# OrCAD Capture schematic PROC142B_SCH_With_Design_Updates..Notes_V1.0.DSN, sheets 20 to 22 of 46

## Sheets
20 19. M.2 INTERFACE: size C; title: M.2 INTERFACE AND CONNECTOR
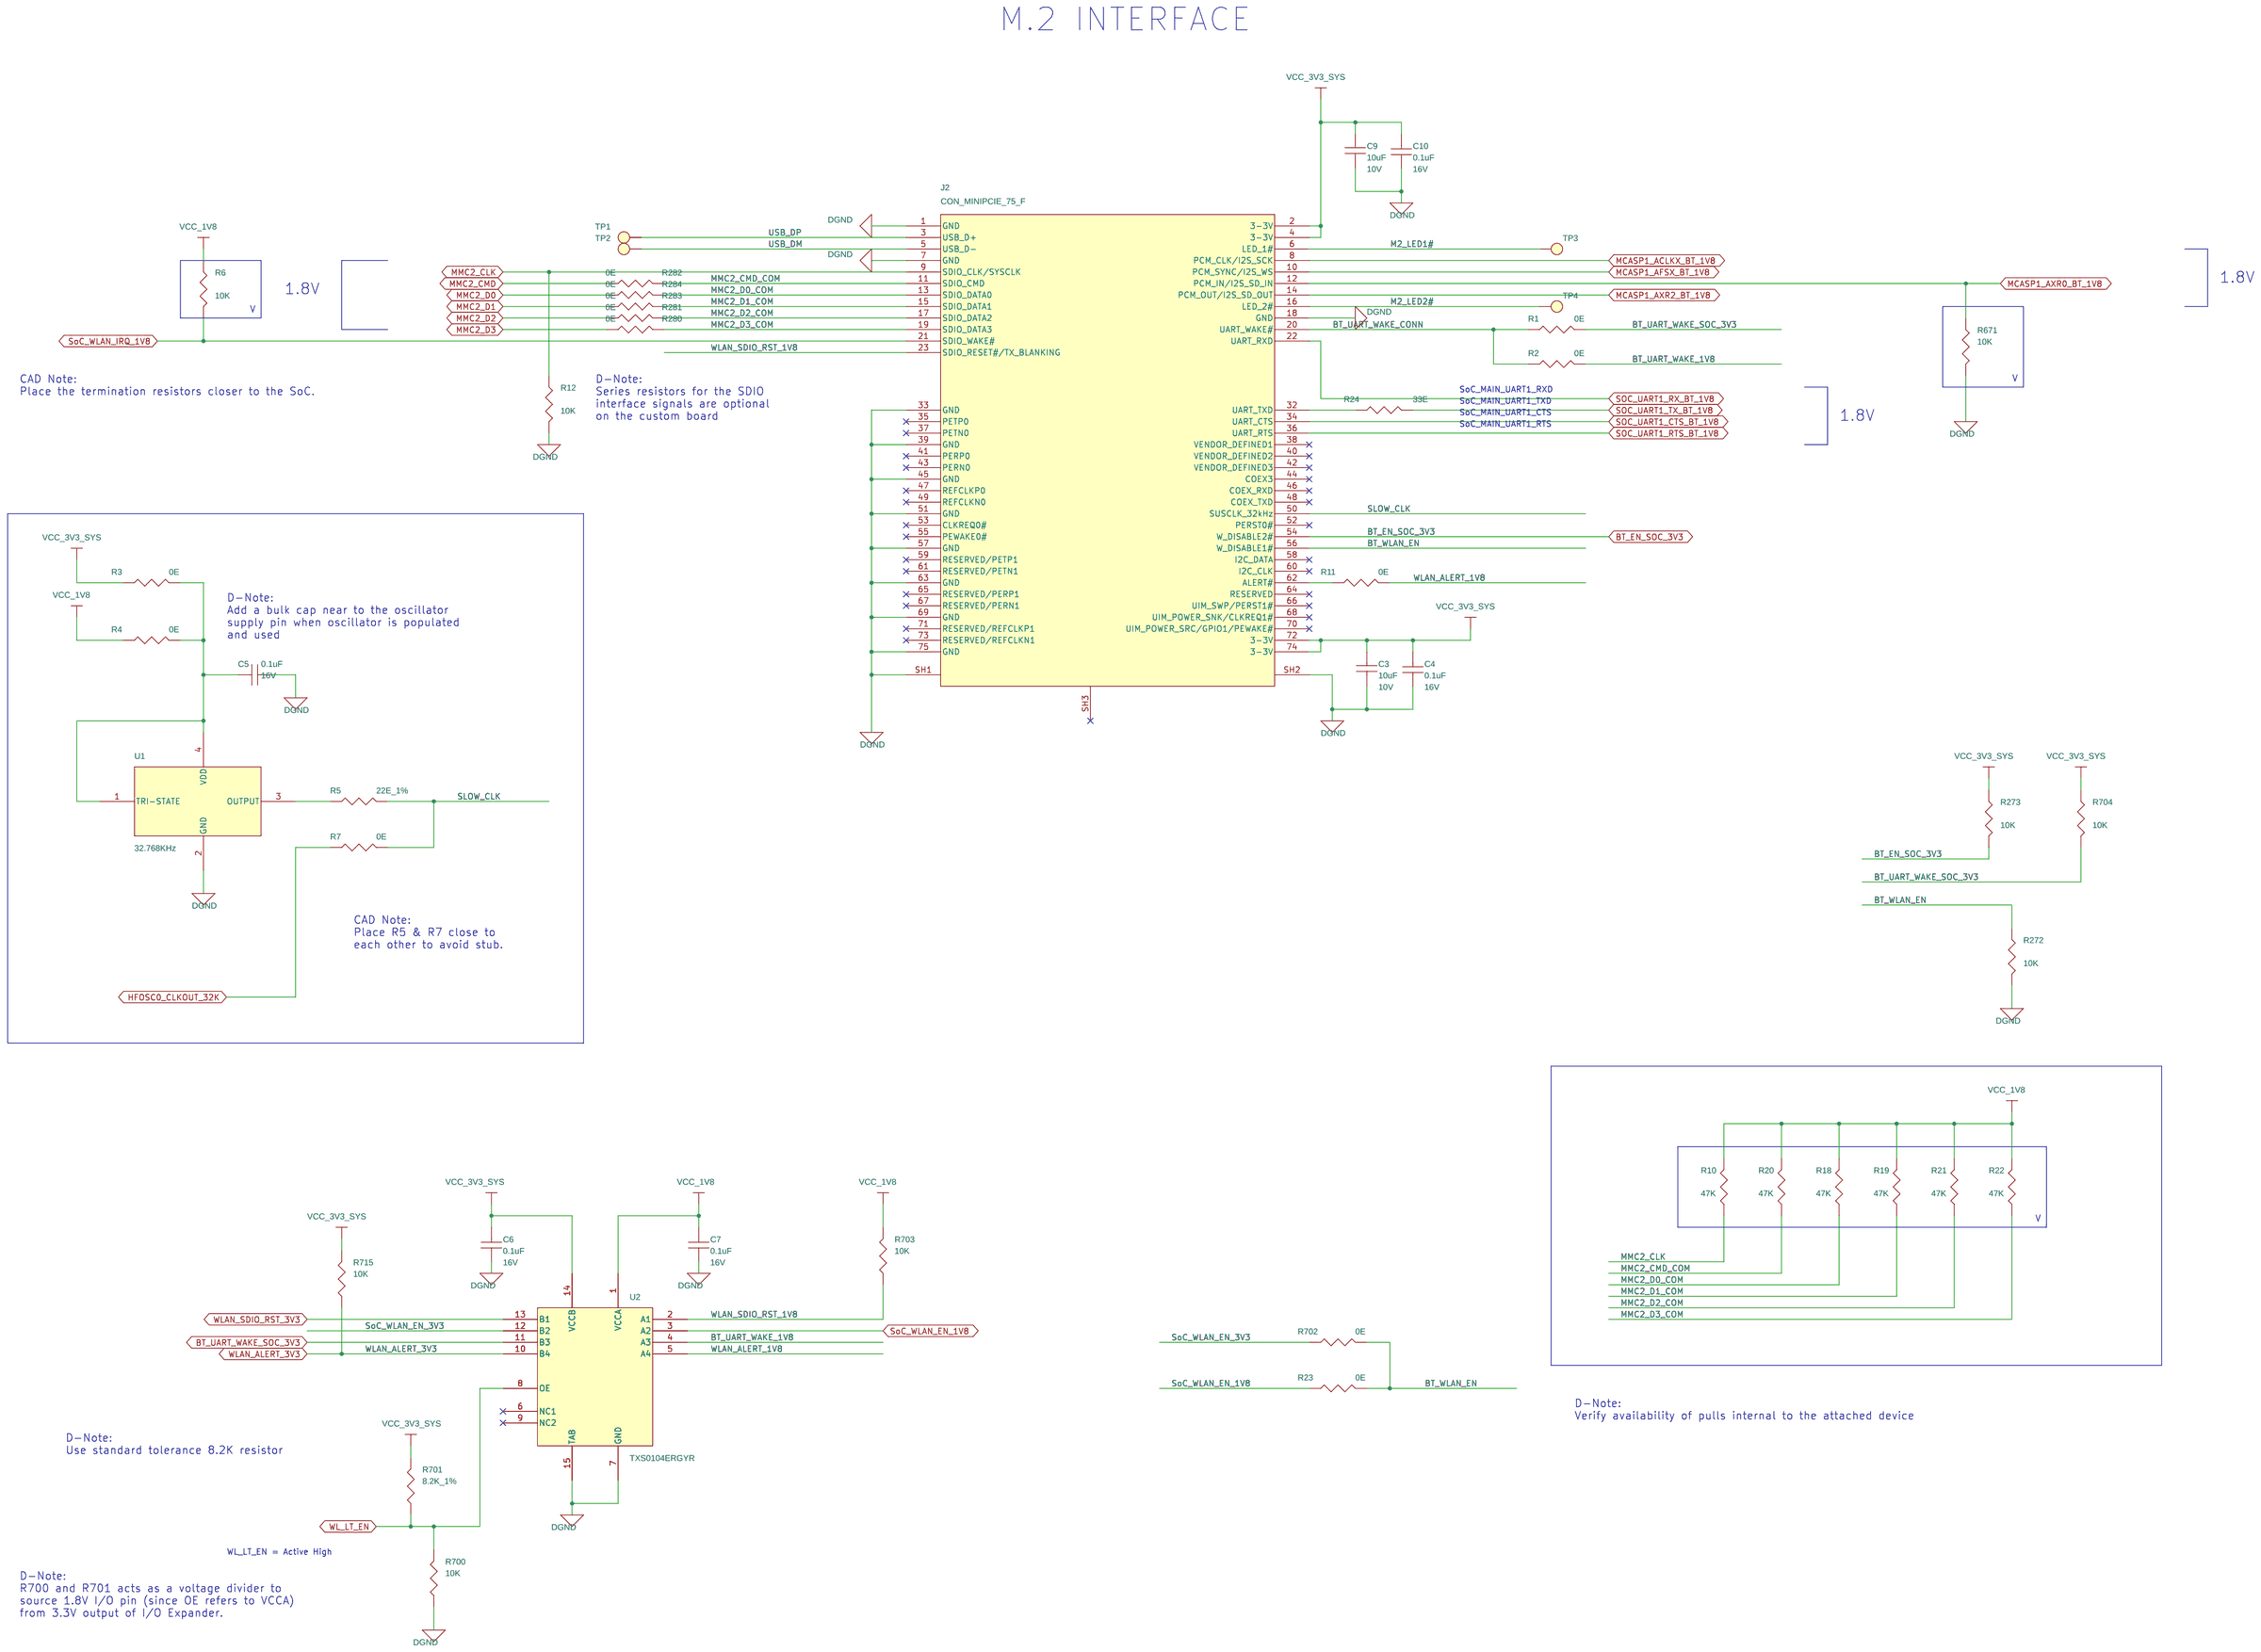
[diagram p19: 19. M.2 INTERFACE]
21 20. eMMC FLASH: size C; title: SOC MMC0.2 INTERFACE AND eMMC FLASH + RESET
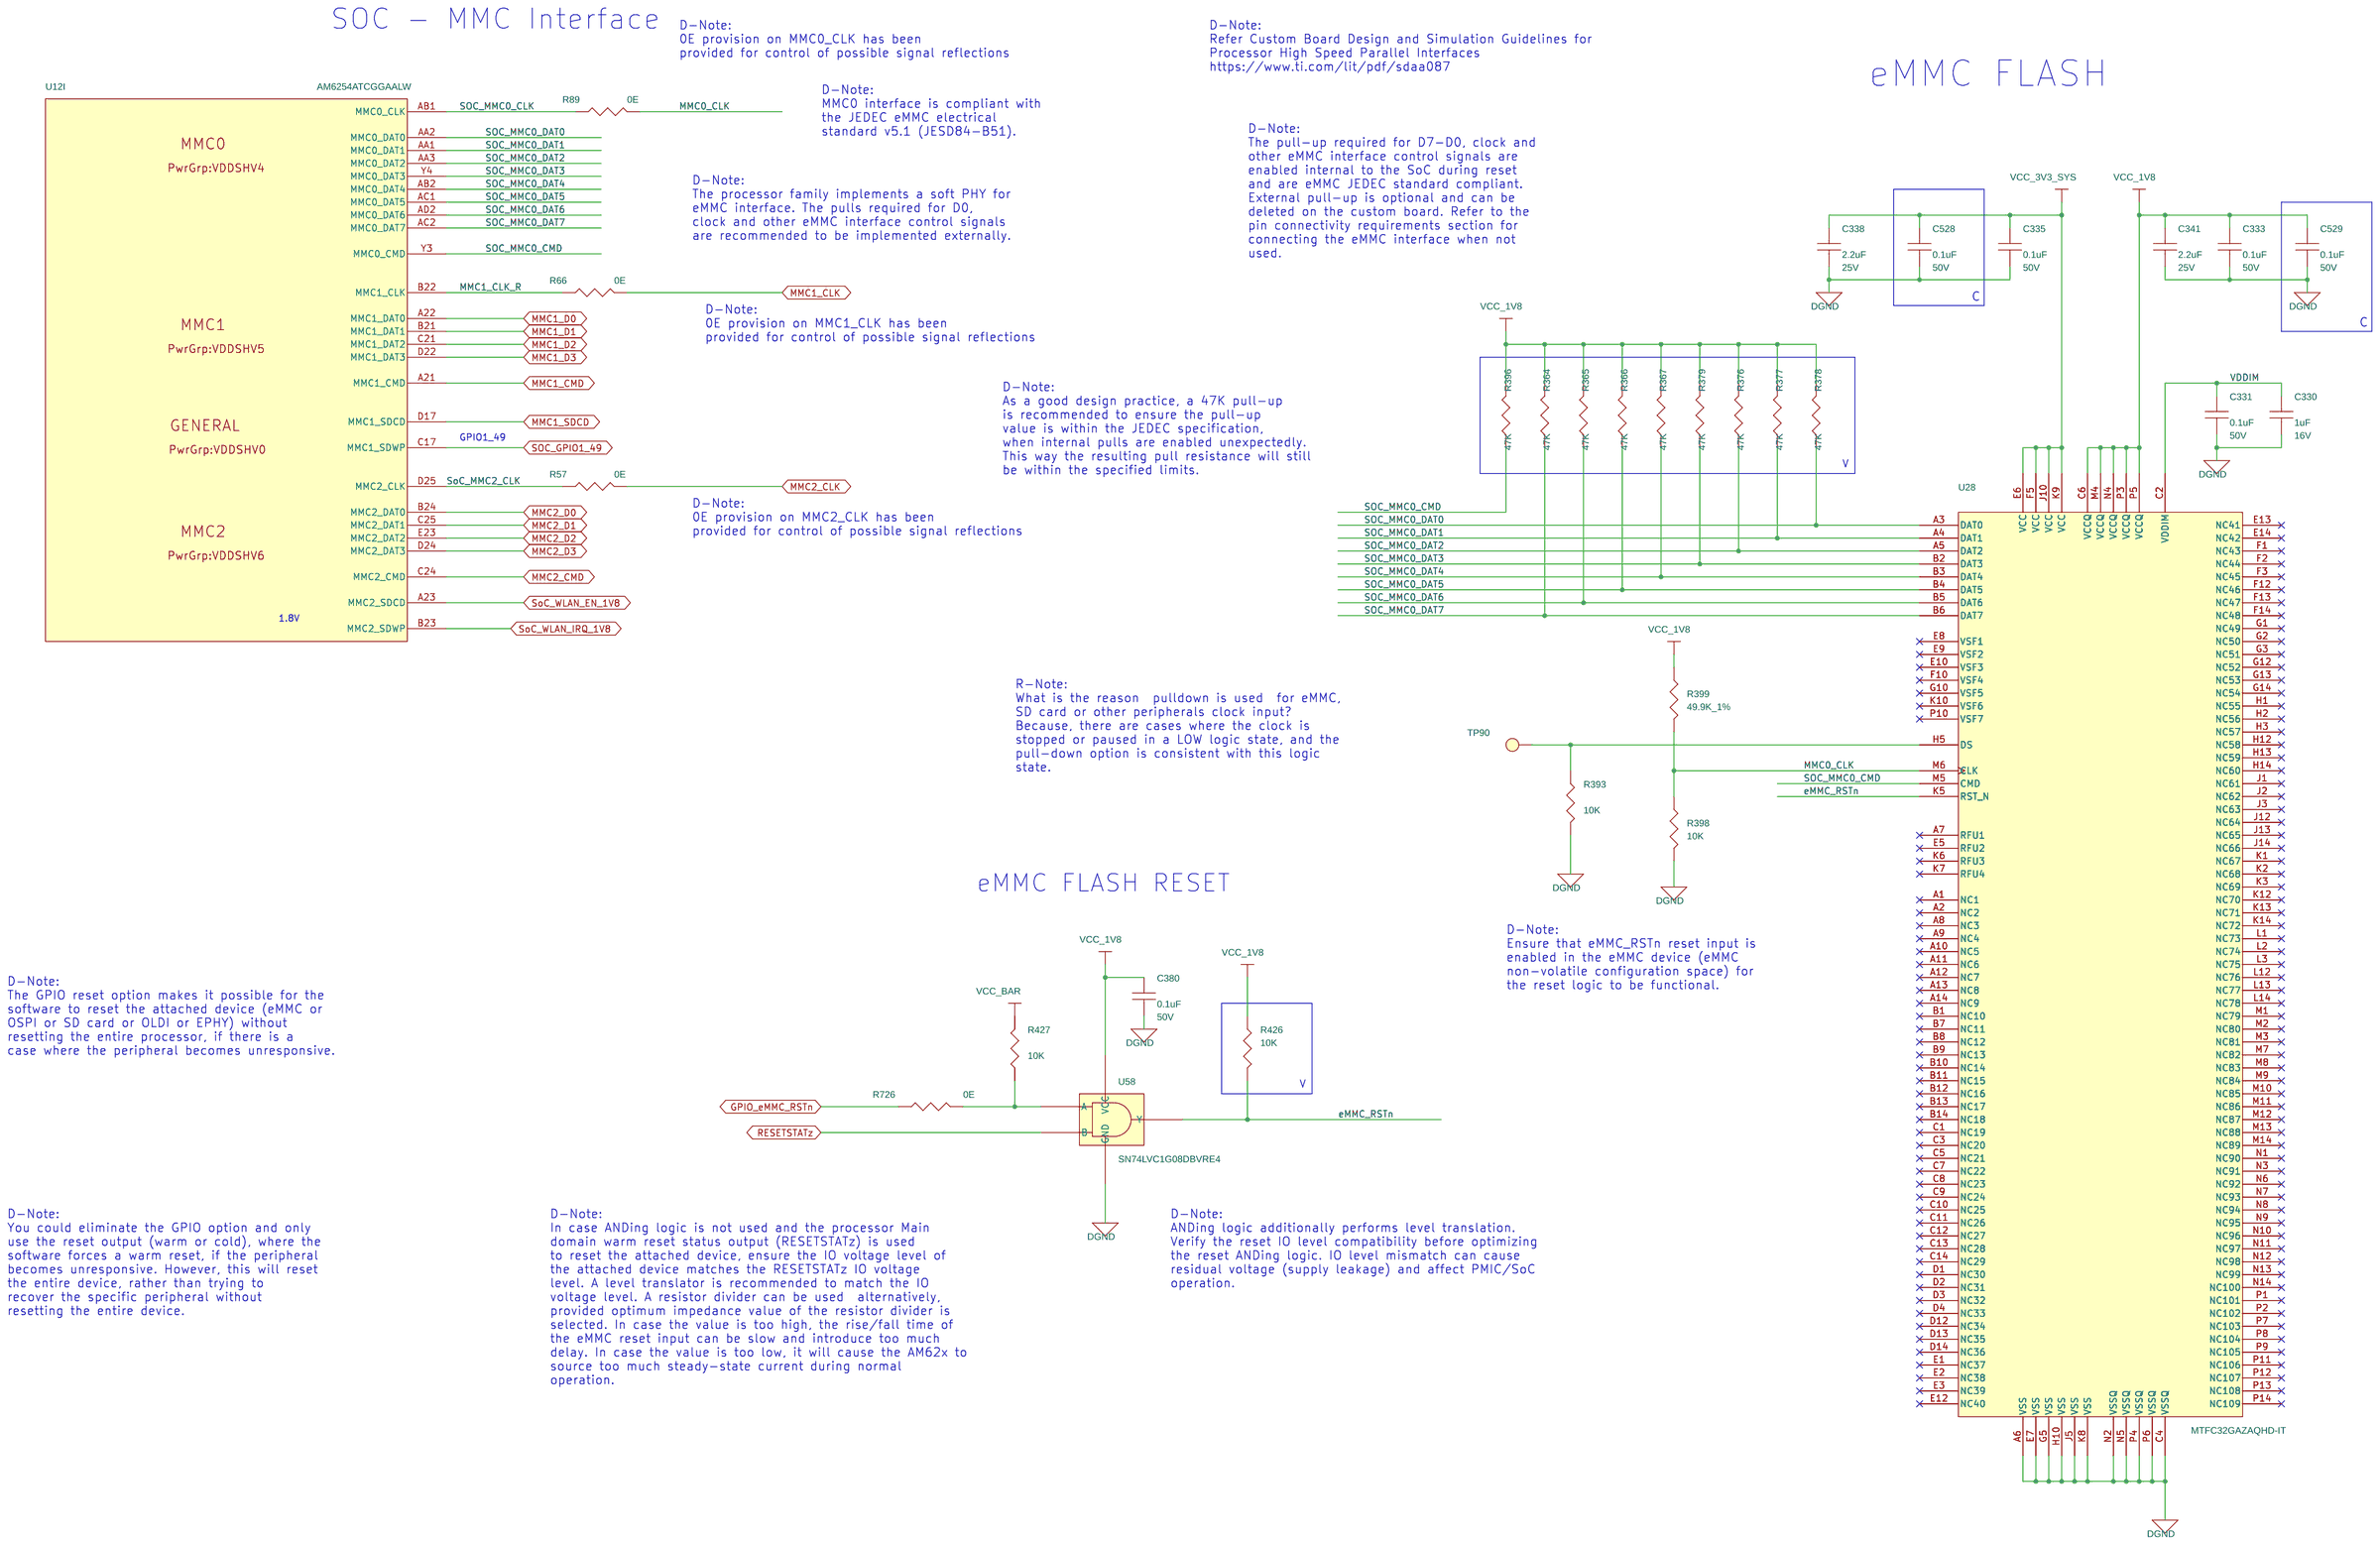
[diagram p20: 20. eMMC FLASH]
22 21. SD CARD INTERFACE: size C; title: SD CARD-LOAD SWITCH, LOAD SWITCH RESET LOGIC AND DATA INTERFACE
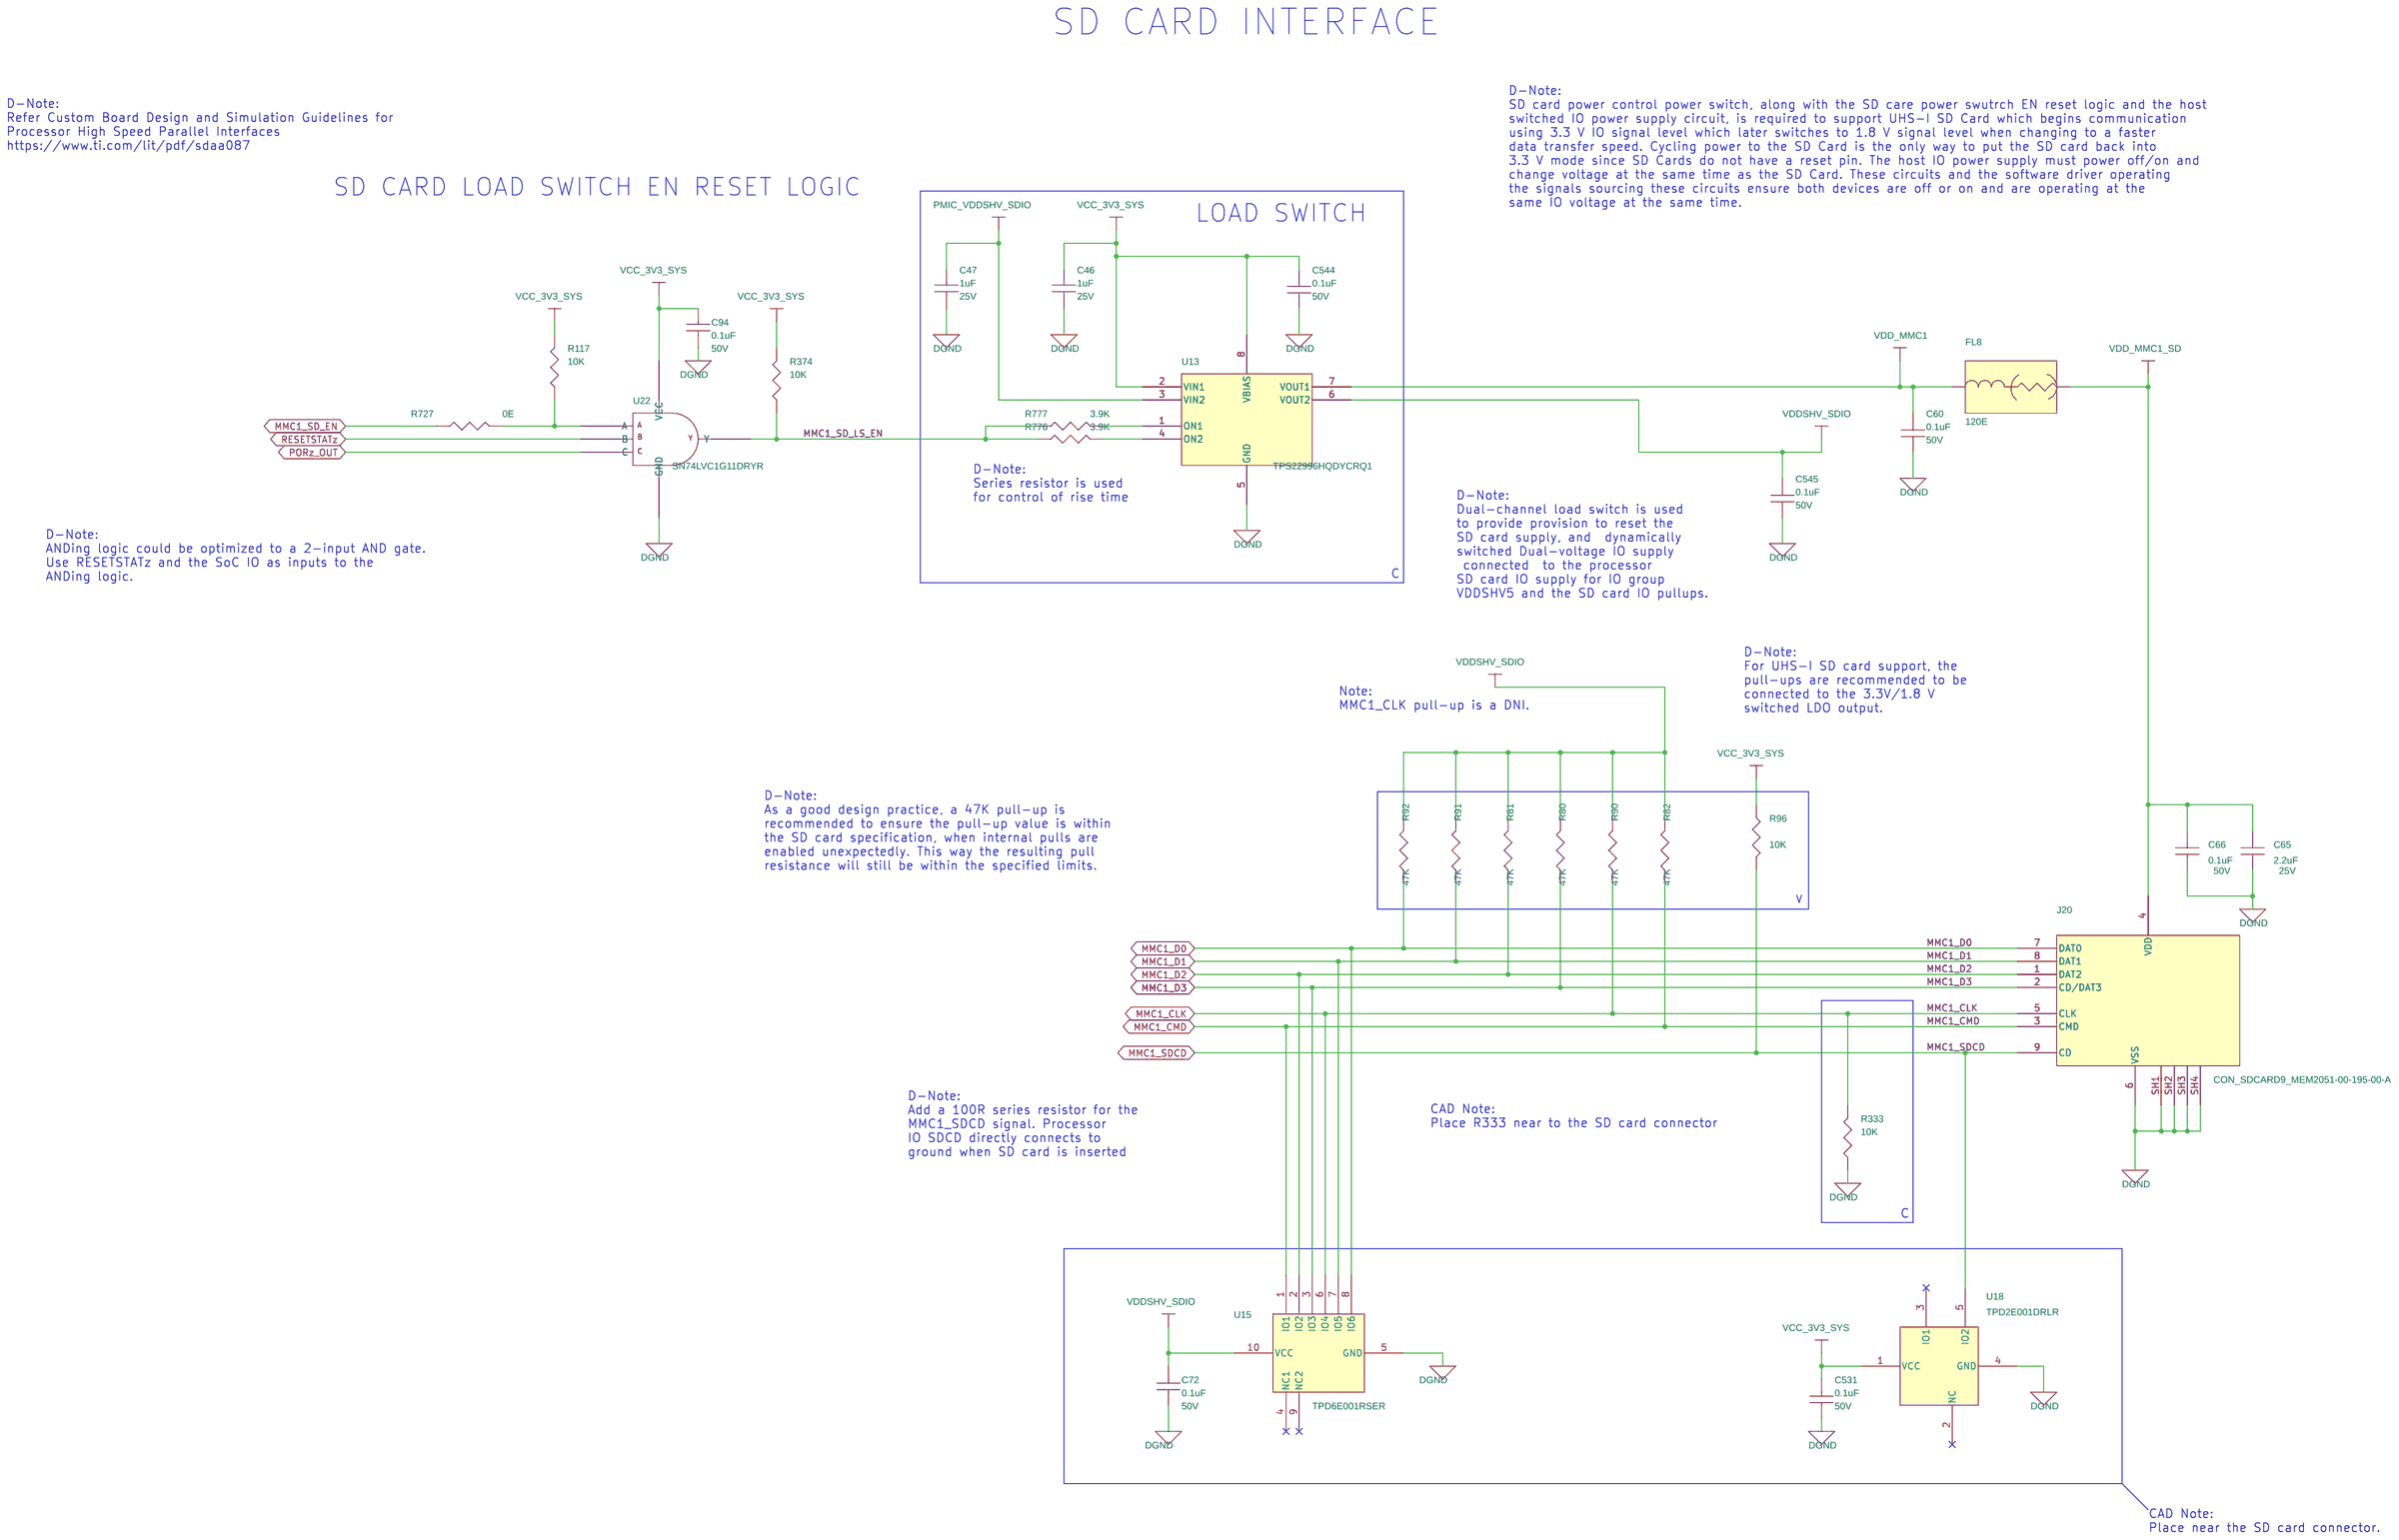
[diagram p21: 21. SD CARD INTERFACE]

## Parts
sheet 19. M.2 INTERFACE
C3  10uF  [CAP0402_0-75]
C4  0.1uF  [CAP0201_0-5]
C5  0.1uF  [CAP0201_0-5]
C6  0.1uF  [CAP0201_0-5]
C7  0.1uF  [CAP0201_0-5]
C9  10uF  [CAP0402_0-75]
C10  0.1uF  [CAP0201_0-5]
J2  CON_MINIPCIE_75_F  [CON_MINIPCI75_2199119-4_S_R_S_3-2_2230]
R1  0E  [RES0201_0-5]
R2  0E  [RES0201_0-5]
R3  0E  [RES0201_0-5]
R4  0E  [RES0201_0-5]
R5  22E_1%  [RES0201_0-5]
R6  10K  [RES0201_0-5]
R7  0E  [RES0201_0-5]
R10  47K  [RES0402_0-5]
R11  0E  [RES0201_0-5]
R12  10K  [RES0201_0-5]
R18  47K  [RES0402_0-5]
R19  47K  [RES0402_0-5]
R20  47K  [RES0402_0-5]
R21  47K  [RES0402_0-5]
R22  47K  [RES0402_0-5]
R23  0E  [RES0201_0-5]
R24  33E  [RES0201_0-5]
R272  10K  [RES0402_0-5]
R273  10K  [RES0402_0-5]
R280  0E  [RES0402_0-5]
R281  0E  [RES0402_0-5]
R282  0E  [RES0402_0-5]
R283  0E  [RES0402_0-5]
R284  0E  [RES0402_0-5]
R671  10K  [RES0402_0-5]
R700  10K  [RES0201_0-5]
R701  8.2K_1%  [RES0201_0-5]
R702  0E  [RES0201_0-5]
R703  10K  [RES0201_0-5]
R704  10K  [RES0402_0-5]
R715  10K  [RES0201_0-5]
TP1  TP20_SMD  [TP20_SMD]
TP2  TP20_SMD  [TP20_SMD]
TP3  TP20_SMD  [TP20_SMD]
TP4  TP20_SMD  [TP20_SMD]
U1  32.768KHz  [OSC4_ASDK_105X85_SMD]
U2  TXS0104ERGYR  [QFN14_19-68_145X145]
sheet 20. eMMC FLASH
C330  1uF  [CAP0201_0-5]
C331  0.1uF  [CAP0402_0-75]
C333  0.1uF  [CAP0402_0-75]
C335  0.1uF  [CAP0402_0-75]
C338  2.2uF  [CAP0402_0-75]
C341  2.2uF  [CAP0402_0-75]
C380  0.1uF  [CAP0402_0-75]
C528  0.1uF  [CAP0402_0-75]
C529  0.1uF  [CAP0402_0-75]
R57  0E  [RES0201_0-5]
R66  0E  [RES0201_0-5]
R89  0E  [RES0201_0-5]
R364  47K  [RES0402_0-5]
R365  47K  [RES0402_0-5]
R366  47K  [RES0402_0-5]
R367  47K  [RES0402_0-5]
R376  47K  [RES0402_0-5]
R377  47K  [RES0402_0-5]
R378  47K  [RES0402_0-5]
R379  47K  [RES0402_0-5]
R393  10K  [RES0201_0-5]
R396  47K  [RES0402_0-5]
R398  10K  [RES0201_0-5]
R399  49.9K_1%  [RES0402_0-5]
R426  10K  [RES0402_0-5]
R427  10K  [RES0201_0-5]
R726  0E  [RES0402_0-5]
TP90  TP20_SMD  [TP20_SMD]
U28  MTFC32GAZAQHD-IT  [VFBGA153_19-68_460X520_0-9]
U58  SN74LVC1G08DBVRE4  [SOT23-5]
sheet 21. SD CARD INTERFACE
C46  1uF  [CAP0402_0-75]
C47  1uF  [CAP0402_0-75]
C60  0.1uF  [CAP0402_0-75]
C65  2.2uF  [CAP0402_0-75]
C66  0.1uF  [CAP0402_0-75]
C72  0.1uF  [CAP0402_0-75]
C94  0.1uF  [CAP0402_0-75]
C531  0.1uF  [CAP0402_0-75]
C544  0.1uF  [CAP0402_0-75]
C545  0.1uF  [CAP0402_0-75]
FL8  120E  [EMIFIL_BLM15A_0402_0-6]
J20  CON_SDCARD9_MEM2051-00-195-00-A  [CON_SD9_MEM2051-00-195-00_S_R_S_2-1]
R80  47K  [RES0402_0-5]
R81  47K  [RES0402_0-5]
R82  47K  [RES0402_0-5]
R90  47K  [RES0402_0-5]
R91  47K  [RES0402_0-5]
R92  47K  [RES0402_0-5]
R96  10K  [RES0402_0-5]
R117  10K  [RES0201_0-5]
R333  10K  [RES0201_0-5]
R374  10K  [RES0201_0-5]
R727  0E  [RES0402_0-5]
R776  3.9K  [RES0402_0-5]
R777  3.9K  [RES0402_0-5]
U13  TPS22996HQDYCRQ1  [SOT5X3-8_0-6]
U15  TPD6E001RSER  [UQFN10_19-68_80X60_0-6]
U18  TPD2E001DRLR  [SOT553-5_0-6]
U22  SN74LVC1G11DRYR  [SON6_SN74LVC2G17_40X60_0-6]
sheet 43. HDMI INTERFACE
U12  AM6254ATCGGAALW  [BGA425_19-68_510X510_0-7]  (sections A,B,C,D,E,F,G,H,I,J,K,L,M,N,O,P,Q,R)

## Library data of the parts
C3 C9 = CAP: CAP CERAMIC 10uF 10V 20% X5R 0402; Chkd/date: MANIRAJA/300520; Crtd /date: ALVY/260520; Custom_Duty: 15%; Customs_HS_Code: 85322990; Distributor_name: DIGIKEY; Distributor_part_number: 490-GRM155R61A106ME11DTR-ND; Footprint Path: Y:\MIS_DATABASE\Library\ALTIUM_TOOL\PCB_FOOTPRINTS\Altium_Footprint_Lib.PcbLib; Height: 0.55MM; Library Path: Y:\MIS_DATABASE\Library\ALTIUM_TOOL\SCHEMATICS_PARTS\MS_DISCRETE_Library.schlib; Mfr_name: MURATA; Mfr_part_number: GRM155R61A106ME11D; Mistral Part No: 120013110019-R; Package: 0402; Part_type: CAPACITORS\CERAMIC; Project: QCS610_NANOSOM; RoHS: RoHS; Temperature: -55°C+85°C; Tolerance: 20%; Voltage: 10V; Wattage: NA; Weight: 3.1mg; Datasheet: Y:\MIS_DATABASE\DATASHEETS\CAPACITORS\MURATA-GXX-SER_NOV17.PDF
C4-C7 C10 = CAP: CAP CERAMIC 0.1uF 16V 10% X5R 0201; Alt_Mfr_name: YAGEO AMERICA; Alt_Mfr_part_number: CC0402KRX5R8BB104; Chkd/date: MANIRAJA/230118; Crtd /date: MANIRAJA/230118; Custom_Duty: 15%; Customs_HS_Code: 85322990; Distributor_name: DIGIKEY; Distributor_part_number: 490-14305-1-ND; Footprint Path: Y:\MIS_DATABASE\Library\ALTIUM_TOOL\PCB_FOOTPRINTS\Altium_Footprint_Lib.PcbLib; Height: 0.33MM; Library Path: Y:\MIS_DATABASE\Library\ALTIUM_TOOL\SCHEMATICS_PARTS\MS_DISCRETE_Library.schlib; Mfr_name: MURATA; Mfr_part_number: GRM033R61C104KE14D; Mistral Part No: 120009030072-R; Package: 0201; Part_type: CAPACITORS\CERAMIC; Project: TI_MAXIE_CPB; RoHS: RoHS; Temperature: -55°C+85°C; Tolerance: 10%; Voltage: 16V; Wattage: NA; Weight: 0.33mg; Datasheet: Y:\MIS_DATABASE\DATASHEETS\CAPACITORS\GRM033R61C104KE14.PDF
J2 = CON_PCI_75_2199119-4_2230: CON MINIPCI 75POS 0.50MM PITCH FEMALE RT SMD; Chkd/date: ALVY/300521; Crtd /date: ALVY/300521; Custom_Duty: 24%; Customs_HS_Code: 85369090; Distributor_name: DIGIKEY; Distributor_part_number: A115900CT-ND; Footprint Path: Y:\MIS_DATABASE\Library\ALTIUM_TOOL\PCB_FOOTPRINTS\Altium_Footprint_Lib.PcbLib; Height: 3.20MM; Library Path: Y:\MIS_DATABASE\Library\ALTIUM_TOOL\SCHEMATICS_PARTS\MS_CONNECTOR_Library.schlib; Mfr_name: TE CONNECTIVITY; Mfr_part_number: 2199119-4_2230; Mistral Part No: 150021030016-R; Package: SMD; Part_type: CONNECTOR\PCI; Project: VOLTA_CHARGER V5; RoHS: RoHS; Temperature: -40°C+80°C; Tolerance: NA; Voltage: NA; Wattage: NA; Weight: 506mg; Datasheet: Y:\MIS_DATABASE\DATASHEETS\CONNECTORS\2199119.PDF
R1-R4 R7 R11 R23 R702 = RESISTOR: RES 0E 1/20W 5% 0201; Chkd/date: NAVEED/301214; Crtd /date: MUDDU/120710; Custom_Duty: 15%; Customs_HS_Code: 85332119; Distributor_name: DIGIKEY; Distributor_part_number: 311-0.0NCT-ND; Footprint Path: Y:\MIS_DATABASE\Library\ALTIUM_TOOL\PCB_FOOTPRINTS\Altium_Footprint_Lib.PcbLib; Height: 0.26MM; Library Path: Y:\MIS_DATABASE\Library\ALTIUM_TOOL\SCHEMATICS_PARTS\MS_DISCRETE_Library.schlib; Mfr_name: YAGEO AMERICA; Mfr_part_number: RC0201JR-070RL; Mistral Part No: 110010070067-R; Package: 0201; Part_type: RESISTORS\FIXED; Project: PB_BUGBASE; RoHS: RoHS; Temperature: -55°C+125°C; Tolerance: 5%; Voltage: NA; Wattage: 1/20W; Weight: 0.17mg; Datasheet: Y:\MIS_DATABASE\DATASHEETS\RESISTORS\RCXXXXL-SER_MAR18.PDF
R5 = RESISTOR: RES 22E 1/20W 1% 0201; Chkd/date: MAZHAR/140709; Crtd /date: MAZHAR/220807; Custom_Duty: 15%; Customs_HS_Code: 85332119; Distributor_name: DIGIKEY; Distributor_part_number: P22.0ABCT-ND; Footprint Path: Y:\MIS_DATABASE\Library\ALTIUM_TOOL\PCB_FOOTPRINTS\Altium_Footprint_Lib.PcbLib; Height: 0.26MM; Library Path: Y:\MIS_DATABASE\Library\ALTIUM_TOOL\SCHEMATICS_PARTS\MS_DISCRETE_Library.schlib; Mfr_name: PANASONIC-ECG; Mfr_part_number: ERJ-1GEF22R0C; Mistral Part No: 110009030522-R; Package: 0201; Part_type: RESISTORS\FIXED; Project: V8TS; RoHS: RoHS; Temperature: -55°C+125°C; Tolerance: 1%; Voltage: NA; Wattage: 1/20W; Weight: 0.15mg; Datasheet: Y:\MIS_DATABASE\DATASHEETS\RESISTORS\PAN-ERJSER_NOV17.PDF
R6 R12 R117 R333 R374 R393 R398 R427 R700 R703 R715 = RESISTOR: RES 10K 1/20W 5% 0201; Chkd/date: MANIRAJA/050517; Crtd /date: MANIRAJA/050517; Custom_Duty: 15%; Customs_HS_Code: 85332119; Distributor_name: DIGIKEY; Distributor_part_number: 311-10KNCT-ND; Footprint Path: Y:\MIS_DATABASE\Library\ALTIUM_TOOL\PCB_FOOTPRINTS\Altium_Footprint_Lib.PcbLib; Height: 0.26MM; Library Path: Y:\MIS_DATABASE\Library\ALTIUM_TOOL\SCHEMATICS_PARTS\MS_DISCRETE_Library.schlib; Mfr_name: YAGEO AMERICA; Mfr_part_number: RC0201JR-0710KL; Mistral Part No: 110010070051-R; Package: 0201; Part_type: RESISTORS\FIXED; Project: GOLDEN-I LITE; RoHS: RoHS; Temperature: -55°C+125°C; Tolerance: 5%; Voltage: NA; Wattage: 1/20W; Weight: 0.17mg; Datasheet: Y:\MIS_DATABASE\DATASHEETS\RESISTORS\RCXXXXL-SER_MAR18.PDF
R10 R18-R22 R80-R82 R90-R92 R364-R367 R376-R379 R396 = RESISTOR: RES 47K 1/10W 5% 0402; Chkd/date: VASANTHA/281216; Crtd /date: MAZHAR/120505; Custom_Duty: 15%; Customs_HS_Code: 85332119; Distributor_name: DIGIKEY; Distributor_part_number: P47KJCT-ND; Footprint Path: Y:\MIS_DATABASE\Library\ALTIUM_TOOL\PCB_FOOTPRINTS\Altium_Footprint_Lib.PcbLib; Height: 0.40MM; Library Path: Y:\MIS_DATABASE\Library\ALTIUM_TOOL\SCHEMATICS_PARTS\MS_DISCRETE_Library.schlib; Mfr_name: PANASONIC-ECG; Mfr_part_number: ERJ-2GEJ473X; Mistral Part No: 110009030882-R; Package: 0402; Part_type: RESISTORS\FIXED; Project: CTP02_REVA_BASE; RoHS: RoHS; Temperature: -55°C+155°C; Tolerance: 5%; Voltage: NA; Wattage: 1/10W; Weight: 0.8mg; Datasheet: Y:\MIS_DATABASE\DATASHEETS\RESISTORS\PAN-ERJSER_NOV17.PDF
R24 = RESISTOR: RES 33E 1/20W 5% 0201; Chkd/date: VASANTHA/061216; Crtd /date: MAZHAR/170505; Custom_Duty: 15%; Customs_HS_Code: 85332119; Distributor_name: DIGIKEY; Distributor_part_number: P33AGCT-ND; Footprint Path: Y:\MIS_DATABASE\Library\ALTIUM_TOOL\PCB_FOOTPRINTS\Altium_Footprint_Lib.PcbLib; Height: 0.26MM; Library Path: Y:\MIS_DATABASE\Library\ALTIUM_TOOL\SCHEMATICS_PARTS\MS_DISCRETE_Library.schlib; Mfr_name: PANASONIC-ECG; Mfr_part_number: ERJ-1GEJ330C; Mistral Part No: 110010070052-R; Package: 0201; Part_type: RESISTORS\FIXED; Project: G4SLIM; RoHS: RoHS; Temperature: -55°C+125°C; Tolerance: 5%; Voltage: NA; Wattage: 1/20W; Weight: 0.15mg; Datasheet: Y:\MIS_DATABASE\DATASHEETS\RESISTORS\PAN-ERJXGE-FEB06.PDF
R96 R272 R273 R426 R671 R704 = RESISTOR: RES 10K 1/16W 5% 0402; Chkd/date: MANIRAJA/120219; Crtd /date: MANIRAJA/120219; Custom_Duty: 15%; Customs_HS_Code: 85332119; Distributor_name: DIGIKEY; Distributor_part_number: 541-10KJCT-ND; Footprint Path: Y:\MIS_DATABASE\Library\ALTIUM_TOOL\PCB_FOOTPRINTS\Altium_Footprint_Lib.PcbLib; Height: 0.40MM; Library Path: Y:\MIS_DATABASE\Library\ALTIUM_TOOL\SCHEMATICS_PARTS\MS_DISCRETE_Library.schlib; Mfr_name: VISHAY; Mfr_part_number: CRCW040210K0JNED; Mistral Part No: 110011060021-R; Package: 0402; Part_type: RESISTORS\FIXED; Project: NEXTNAV_ORBIT_MODULE; RoHS: RoHS; Temperature: -55°C+155°C; Tolerance: 5%; Voltage: NA; Wattage: 1/16W; Weight: 0.65mg; Datasheet: Y:\MIS_DATABASE\DATASHEETS\RESISTORS\CRCW0603.PDF
R280-R284 R726 R727 = RESISTOR: RES 0E 1/16W JUMPER 0402; Chkd/date: VASANTHA/201216; Crtd /date: MUDDU/190810; Custom_Duty: 15%; Customs_HS_Code: 85332119; Distributor_name: DIGIKEY; Distributor_part_number: 541-0.0JCT-ND; Footprint Path: Y:\MIS_DATABASE\Library\ALTIUM_TOOL\PCB_FOOTPRINTS\Altium_Footprint_Lib.PcbLib; Height: 0.40MM; Library Path: Y:\MIS_DATABASE\Library\ALTIUM_TOOL\SCHEMATICS_PARTS\MS_DISCRETE_Library.schlib; Mfr_name: VISHAY; Mfr_part_number: CRCW04020000Z0ED; Mistral Part No: 110010080019-R; Package: 0402; Part_type: RESISTORS\FIXED; Project: PB_BUGBASE; RoHS: RoHS; Temperature: -55°C+155°C; Tolerance: NA; Voltage: NA; Wattage: 1/16W; Weight: 0.65mg; Datasheet: Y:\MIS_DATABASE\DATASHEETS\RESISTORS\CRCW0603.PDF
R701 = RESISTOR: RES 8.2K 1/20W 1% 0201; Chkd/date: SUHAS/230910; Crtd /date: MUDDU/060710; Custom_Duty: 15%; Customs_HS_Code: 85332119; Distributor_name: DIGIKEY; Distributor_part_number: 541-8.20KAABCT-ND; Footprint Path: Y:\MIS_DATABASE\Library\ALTIUM_TOOL\PCB_FOOTPRINTS\Altium_Footprint_Lib.PcbLib; Height: 0.28MM; Library Path: Y:\MIS_DATABASE\Library\ALTIUM_TOOL\SCHEMATICS_PARTS\MS_DISCRETE_Library.schlib; Mfr_name: VISHAY; Mfr_part_number: CRCW02018K20FKED; Mistral Part No: 110010070001-R; Package: 0201; Part_type: RESISTORS\FIXED; Project: PB_BUGBASE; RoHS: RoHS; Temperature: -55°C+155°C; Tolerance: 1%; Voltage: NA; Wattage: 1/20W; Weight: 0.17mg; Datasheet: Y:\MIS_DATABASE\DATASHEETS\RESISTORS\CRCW0201.PDF
TP1-TP4 TP90 = TESTPOINT: TESTPOINT CIR 20 SMD; Chkd/date: SHREESHAIL/171006; Crtd /date: MAZHAR/171006; Custom_Duty: NA; Customs_HS_Code: NA; Distributor_name: NA; Distributor_part_number: NA; Footprint Path: Y:\MIS_DATABASE\Library\ALTIUM_TOOL\PCB_FOOTPRINTS\Altium_Footprint_Lib.PcbLib; Height: NA; Library Path: Y:\MIS_DATABASE\Library\ALTIUM_TOOL\SCHEMATICS_PARTS\MS_DISCRETE_Library.schlib; MECHANICAL 3D STEP FILE: NA; Mfr_name: LOCAL; Mistral Part No: NA; Package: SMD; Project: BT MODULE_CSRBC04; RoHS: NA; Temperature: NA; Tolerance: NA; Voltage: NA; Wattage: NA; Weight: NA; Datasheet: NA
U1 = OSC4_ASFL3: OSC 32.768KHz 1.8V SMD; Chkd/date: SUHAS/100710; Crtd /date: USMAN/020409; Custom_Duty: 24%; Customs_HS_Code: 85437099; Distributor_name: DIGIKEY; Distributor_part_number: 535-10003-1-ND; Height: 0.95MM; Mfr_name: ABRACON; Mfr_part_number: ASDK2-32.768KHZ-LRT; Mistral Part No: 130009031113-R; Package: SMD; Part_type: OSCILLATORS; Project: AXON; RoHS: RoHS; Temperature: -40°C+85°C; Voltage: 1.8V; Weight: NA; Datasheet: Y:\MIS_DATABASE\DATASHEETS\MISC\CRY_OSC\ASDK.PDF
U2 = TXS0104ERGYR_QFN14: IC 4-BIT BIDIRECTIONAL VOLTAGE-LEVEL TRANSLATOR QFN14; Chkd/date: SHREESHAIL/170108; Crtd /date: SHREESHAIL/170108; Custom_Duty: 15%; Customs_HS_Code: 85423100; Distributor_name: DIGIKEY; Distributor_part_number: 296-20698-1-ND; Height: 1.00MM; Mfr_name: TEXAS INSTRUMENTS; Mistral Part No: 141009030362-R; Package: QFN14; Part_type: ICS\INTERFACE; Project: HS100RD; RoHS: Sb/ Br FREE; Datasheet: Y:\MIS_DATABASE\DATASHEETS\ICS\INTERFACE\TXS0104E.PDF
C330 = CAP: CAP CERAMIC 1uF 16V 20% X5R 0201; Chkd/date: MANIRAJA/300520; Crtd /date: ALVY/260520; Custom_Duty: 15%; Customs_HS_Code: 85322990; Distributor_name: DIGIKEY; Distributor_part_number: 490-18654-1-ND; Footprint Path: Y:\MIS_DATABASE\Library\ALTIUM_TOOL\PCB_FOOTPRINTS\Altium_Footprint_Lib.PcbLib; Height: 0.39MM; Library Path: Y:\MIS_DATABASE\Library\ALTIUM_TOOL\SCHEMATICS_PARTS\MS_DISCRETE_Library.schlib; Mfr_name: MURATA; Mfr_part_number: GRM033R61C105ME15D; Mistral Part No: 120018090038-R; Package: 0201; Part_type: CAPACITORS\CERAMIC; Project: QCS610_NANOSOM; RoHS: RoHS; Temperature: -55°C+85°C; Tolerance: 20%; Voltage: 16V; Wattage: NA; Weight: 0.33mg; Datasheet: Y:\MIS_DATABASE\DATASHEETS\CAPACITORS\GRM033R61C105ME15.PDF
C60 C66 C72 C94 C331 C333 C335 C380 C528 C529 C531 C544 C545 = CAP: CAP CERAMIC 0.1uF 50V 10% X7R 0402; Alt_Mfr_name: YAGEO AMERICA; Alt_Mfr_part_number: CC0402KRX5R8BB104; Chkd/date: MANIRAJA/261020; Crtd /date: ALVY/211020; Custom_Duty: 15%; Customs_HS_Code: 85322990; Distributor_name: DIGIKEY; Distributor_part_number: 490-10700-1-ND; Footprint Path: Y:\MIS_DATABASE\Library\ALTIUM_TOOL\PCB_FOOTPRINTS\Altium_Footprint_Lib.PcbLib; Height: 0.55MM; Library Path: Y:\MIS_DATABASE\Library\ALTIUM_TOOL\SCHEMATICS_PARTS\MS_DISCRETE_Library.schlib; Mfr_name: MURATA; Mfr_part_number: GRM155R71H104KE14D; Mistral Part No: 120011100014-R; Package: 0402; Part_type: CAPACITORS\CERAMIC; Project: J7_CP; RoHS: RoHS; Temperature: -55°C+125°C; Tolerance: 10%; Voltage: 50V; Wattage: NA; Weight: 3.1mg; Datasheet: Y:\MIS_DATABASE\DATASHEETS\CAPACITORS\GRM155R71H104KE14.PDF
C65 C338 C341 = CAP: CAP CERAMIC 2.2uF 25V 10% X5R 0402; Chkd/date: ALVY/010721; Crtd /date: MANIRAJA/010721; Custom_Duty: 15%; Customs_HS_Code: 85322990; Distributor_name: DIGIKEY; Distributor_part_number: 490-12703-1-ND; Footprint Path: Y:\MIS_DATABASE\Library\ALTIUM_TOOL\PCB_FOOTPRINTS\Altium_Footprint_Lib.PcbLib; Height: 0.70MM; Library Path: Y:\MIS_DATABASE\Library\ALTIUM_TOOL\SCHEMATICS_PARTS\MS_DISCRETE_Library.schlib; Mfr_name: MURATA; Mfr_part_number: GRM155R61E225KE11D; Mistral Part No: 120015120001-R; Package: 0402; Part_type: CAPACITORS\CERAMIC; Project: TI_AM263X_CC; RoHS: RoHS; Temperature: -55°C+85°C; Tolerance: 10%; Voltage: 25V; Wattage: NA; Weight: 1.5mg; Datasheet: Y:\MIS_DATABASE\DATASHEETS\CAPACITORS\GRM155R61E225KE11.PDF
R57 R66 = RESISTOR: RES 0E 1/20W 5% 0201; Chkd/date: NAVEED/301214; Crtd /date: MUDDU/120710; Custom_Duty: 15%; Customs_HS_Code: 85332119; Distributor_name: DIGIKEY; Distributor_part_number: 311-0.0NCT-ND; Footprint Path: Y:\MIS_DATABASE\Library\ALTIUM_TOOL\PCB_FOOTPRINTS\Altium_Footprint_Lib.PcbLib; Height: 0.26MM; Library Path: Y:\MIS_DATABASE\Library\ALTIUM_TOOL\SCHEMATICS_PARTS\MS_DISCRETE_Library.schlib; Mfr_name: YAGEO AMERICA; Mfr_part_number: RC0201JR-070RL; Mistral Part No: 110010070067-R; Package: 0201; Part_type: RESISTORS\FIXED; Project: PB_BUGBASE; RoHS: RoHS; SIGNAL_MODEL: RESISTOR_RES0201_0-5_0E_0E; Temperature: -55°C+125°C; Tolerance: 5%; Voltage: NA; Wattage: 1/20W; Weight: 0.17mg; Datasheet: Y:\MIS_DATABASE\DATASHEETS\RESISTORS\RCXXXXL-SER_MAR18.PDF
R89 = RESISTOR: RES 0E 1/20W 5% 0201; Chkd/date: NAVEED/301214; Crtd /date: MUDDU/120710; Custom_Duty: 15%; Customs_HS_Code: 85332119; Distributor_name: DIGIKEY; Distributor_part_number: 311-0.0NCT-ND; Footprint Path: Y:\MIS_DATABASE\Library\ALTIUM_TOOL\PCB_FOOTPRINTS\Altium_Footprint_Lib.PcbLib; Height: 0.26MM; Library Path: Y:\MIS_DATABASE\Library\ALTIUM_TOOL\SCHEMATICS_PARTS\MS_DISCRETE_Library.schlib; Mfr_name: YAGEO AMERICA; Mfr_part_number: RC0201JR-070RL; Mistral Part No: 110010070067-R; Package: 0201; Part_type: RESISTORS\FIXED; Project: PB_BUGBASE; RoHS: RoHS; SIGNAL_MODEL: RESISTOR_RES0201_0-5_22E_1%_22E_1%; Temperature: -55°C+125°C; Tolerance: 5%; Voltage: NA; Wattage: 1/20W; Weight: 0.17mg; Datasheet: Y:\MIS_DATABASE\DATASHEETS\RESISTORS\RCXXXXL-SER_MAR18.PDF
R399 = RESISTOR: RES 49.9K 1/16W 1% 0402; Chkd/date: MAZHAR/220709; Crtd /date: GEETHA/090606; Custom_Duty: 15%; Customs_HS_Code: 85332119; Distributor_name: DIGIKEY; Distributor_part_number: 311-49.9KLRCT-ND; Footprint Path: Y:\MIS_DATABASE\Library\ALTIUM_TOOL\PCB_FOOTPRINTS\Altium_Footprint_Lib.PcbLib; Height: 0.40MM; Library Path: Y:\MIS_DATABASE\Library\ALTIUM_TOOL\SCHEMATICS_PARTS\MS_DISCRETE_Library.schlib; Mfr_name: YAGEO AMERICA; Mfr_part_number: RC0402FR-0749K9L; Mistral Part No: 110009030902-R; Package: 0402; Part_type: RESISTORS\FIXED; Project: PNAV; RoHS: RoHS; Temperature: -55°C+155°C; Tolerance: 1%; Voltage: NA; Wattage: 1/16W; Weight: 0.65mg; Datasheet: Y:\MIS_DATABASE\DATASHEETS\RESISTORS\RCXXXXL-SER_MAR18.PDF
U28 = MTFC16GAPALBH_TFBGA153: IC 32GB e-MMC MEMORY VFBGA153; Chkd/date: PRAVEEN/010922; Crtd /date: PRAVEEN/010922; Custom_Duty: 15%; Customs_HS_Code: 85423100; Distributor_name: DIGIKEY; Distributor_part_number: 557-MTFC32GAZAQHD-IT-ND; Footprint Path: Y:\MIS_DATABASE\Library\ALTIUM_TOOL\PCB_FOOTPRINTS\Altium_Footprint_Lib.PcbLib; Height: 0.90MM; Library Path: Y:\MIS_DATABASE\Library\ALTIUM_TOOL\SCHEMATICS_PARTS\MS_MISCMEMORY_Library.schlib; Mfr_name: MICRON; Mistral Part No: 141122090001-R; Package: VFBGA153; Part_type: ICS\DIGITAL\MEMORY; Project: J7AHP_SK_BRD; RoHS: RoHS; Temperature: -40°C+95°C; Tolerance: NA; Voltage: NA; Wattage: NA; Weight: NA; Datasheet: Y:\MIS_DATABASE\DATASHEETS\ICS\MEMORY\MTFC64GAZAQHD-IT.PDF
U58 = SN74LVC1G08DBVRE4_SOT23-5: IC SINGLE 2-INPUT POSITIVE AND GATE SOT23-5; Chkd/date: SUHAS/221010; Crtd /date: USMAN/151008; Custom_Duty: 15%; Customs_HS_Code: 85423100; Distributor_name: DIGIKEY; Distributor_part_number: SN74LVC1G08DBVRE4-ND; Height: 1.45MM; Mfr_name: TEXAS INSTRUMENTS; Mistral Part No: 141009060026-R; Part_type: ICS\DIGITAL\GATES; Project: KHAN_MAIN; RoHS: Sb/ Br FREE; Temperature: -40°C+85°C; Datasheet: Y:\MIS_DATABASE\DATASHEETS\ICS\DIGITAL\GATES\SN74LVC1G08.PDF
C46 C47 = CAP: CAP CERAMIC 1uF 25V 10% X6S 0402; Chkd/date: MANIRAJA/140518; Crtd /date: ALVY/140518; Custom_Duty: 15%; Customs_HS_Code: 85322990; Distributor_name: DIGIKEY; Distributor_part_number: 490-10014-1-ND; Footprint Path: Y:\MIS_DATABASE\Library\ALTIUM_TOOL\PCB_FOOTPRINTS\Altium_Footprint_Lib.PcbLib; Height: 0.60MM; Library Path: Y:\MIS_DATABASE\Library\ALTIUM_TOOL\SCHEMATICS_PARTS\MS_DISCRETE_Library.schlib; Mfr_name: MURATA; Mfr_part_number: GRM155C81E105KE11D; Mistral Part No: 120018050004-R; Package: 0402; Part_type: CAPACITORS\CERAMIC; Project: TI_SVB_MAXWELL_DUT; RoHS: RoHS; Temperature: -55°C+105°C; Tolerance: 10%; Voltage: 25V; Wattage: NA; Weight: 6mg; Datasheet: Y:\MIS_DATABASE\DATASHEETS\CAPACITORS\GRM155C81E105KE11X.PDF
FL8 = EMIFILTER_IND: IND FERRITE BEAD CHIP 120E 2A 0402; Chkd/date: NAVEED/241114; Crtd /date: USMAN/170613; Custom_Duty: 24%; Customs_HS_Code: 85369090; Distributor_name: DIGIKEY; Distributor_part_number: 490-9656-1-ND; Footprint Path: Y:\MIS_DATABASE\Library\ALTIUM_TOOL\PCB_FOOTPRINTS\Altium_Footprint_Lib.PcbLib; Height: 0.55MM; Library Path: Y:\MIS_DATABASE\Library\ALTIUM_TOOL\SCHEMATICS_PARTS\MS_FILTER_Library.schlib; Mfr_name: MURATA; Mfr_part_number: BLM15PX121SN1D; Mistral Part No: 130013060022-R; Package: 0402; Part_type: INDUCTOR; Project: GEN_3-8; RoHS: RoHS; Temperature: -55°C+125°C; Tolerance: 25%; Voltage: NA; Wattage: NA; Weight: 1mg; Datasheet: Y:\MIS_DATABASE\DATASHEETS\DISCRETES\INDUCTORS\BLM15-SN1-SER.PDF
J20 = CON_SDCARD9_MEM2075-00-140: CON MICROSD CARD 9POS FEMALE RT SMD; Chkd/date: MANIRAJA/270921; Crtd /date: ALVY/240921; Custom_Duty: 24%; Customs_HS_Code: 85369090; Distributor_name: DIGIKEY; Distributor_part_number: 2073-MEM2051-00-195-00-ACT-ND; Footprint Path: Y:\MIS_DATABASE\Library\ALTIUM_TOOL\PCB_FOOTPRINTS\Altium_Footprint_Lib.PcbLib; Height: 2.05MM; Library Path: Y:\MIS_DATABASE\Library\ALTIUM_TOOL\SCHEMATICS_PARTS\MS_CONNECTOR_Library.schlib; Mfr_name: GCT; Mfr_part_number: MEM2051-00-195-00-A; Mistral Part No: 150021090028-R; Package: SMD; Part_type: CONNECTOR\MEMORY CARD; Project: TI_AM62x SKEVM_BRD; RoHS: RoHS; Temperature: -40°C+85°C; Tolerance: NA; Voltage: NA; Wattage: NA; Weight: 1000mg; Datasheet: Y:\MIS_DATABASE\DATASHEETS\CONNECTORS\MEM2051-00-195-00-A.PDF
R776 R777 = RESISTOR: RES 3.9K 1/16W 5% 0402; Chkd/date: PRADEEP/180725; Crtd /date: SHANKARI/170725; Custom_Duty: 15%; Customs_HS_Code: 85332119; Distributor_name: DIGIKEY; Distributor_part_number: 311-3.9KJRCT-ND; Footprint Path: Y:\MIS_DATABASE\Library\ALTIUM_TOOL\PCB_FOOTPRINTS\Altium_Footprint_Lib.PcbLib; Height: 0.40MM; Library Path: Y:\MIS_DATABASE\Library\ALTIUM_TOOL\SCHEMATICS_PARTS\MS_DISCRETE_Library.schlib; Mfr_name: YAGEO AMERICA; Mfr_part_number: RC0402JR-073K9L; Mistral Part No: 110025070048-R; Package: 0402; Part_type: RESISTORS\FIXED; Project: AM62X_SK_FULTON; RoHS: RoHS; Temperature: -55°C+155°C; Tolerance: 0.05; Voltage: NA; Wattage: 1/16W; Weight: NA; Datasheet: Y:\MIS_DATABASE\DATASHEETS\RESISTORS\RC0402JR-073K9L.PDF
U13 = TPS22996_SOT583-8: IC 5.5V 4A 13MO ON-RESISTANCE DUAL-CHANNEL AUTOMOTIVE LOAD SWITCH SOT583-8; Chkd/date: PRADEEP/170725; Crtd /date: SHANKARI/170725; Custom_Duty: 0.15; Customs_HS_Code: 85423100; Distributor_name: DIGIKEY; Distributor_part_number: 296-TPS22996HQDYCRQ1CT-ND; Footprint Path: Y:\MIS_DATABASE\Library\ALTIUM_TOOL\PCB_FOOTPRINTS\Altium_Footprint_Lib.PcbLib; Height: 0.60MM; Library Path: Y:\MIS_DATABASE\Library\ALTIUM_TOOL\SCHEMATICS_PARTS\MS_MISCPOWER_Library.schlib; Mfr_name: TEXAS INSTRUMENTS; Mistral Part No: 142025070014-R; Package: SOT583-8; Part_type: ICS\POWER\MANAGEMENT; Project: AM62X_SK_FULTON; RoHS: RoHS; Temperature: -40°C+125°C; Tolerance: NA; Voltage: NA; Wattage: NA; Weight: NA; Datasheet: Y:\MIS_DATABASE\DATASHEETS\ICS\POWER\TPS22996HQDYCRQ1.PDF
U15 = TPD6E001RSE_UQFN10: IC 6CH ESD-PROTECTION ARRAY UQFN10; Chkd/date: USMAN/070612; Crtd /date: BAVISH/160811; Custom_Duty: 15%; Customs_HS_Code: 85423100; Distributor_name: DIGIKEY; Distributor_part_number: 296-21888-1-ND; Footprint Path: Y:\MIS_DATABASE\Library\ALTIUM_TOOL\PCB_FOOTPRINTS\Altium_Footprint_Lib.PcbLib; Height: 0.60MM; IBISSP_MODLES: Y:\MIS_DATABASE\IBIS\ICs\INTERFACE\TPD6E001RSE.IBS; Library Path: Y:\MIS_DATABASE\Library\ALTIUM_TOOL\SCHEMATICS_PARTS\MS_MISCINTERFACE_Library.schlib; Mfr_name: TEXAS INSTRUMENTS; Mistral Part No: 141011080020-R; Package: UQFN10; Part_type: ICS\INTERFACE; Project: DM385EVM_BASE-BOARD; RoHS: RoHS; Temperature: -40°C+85°C; Tolerance: NA; Voltage: NA; Wattage: NA; Weight: 7mg; Datasheet: Y:\MIS_DATABASE\DATASHEETS\ICS\INTERFACE\TPD6E001.PDF
U18 = TPD2E001DRLR_SOT-5: IC ESD-PROTECTION DIODE ARRAYS SOT-5; Chkd/date: NAVEED/150714; Crtd /date: MUDDU/250510; Custom_Duty: 15%; Customs_HS_Code: 85423100; Distributor_name: DIGIKEY; Distributor_part_number: 296-21883-1-ND; Footprint Path: Y:\MIS_DATABASE\Library\ALTIUM_TOOL\PCB_FOOTPRINTS\Altium_Footprint_Lib.PcbLib; Height: 0.60MM; Library Path: Y:\MIS_DATABASE\Library\ALTIUM_TOOL\SCHEMATICS_PARTS\MS_FILTER_Library.schlib; Mfr_name: TEXAS INSTRUMENTS; Mistral Part No: 140110060007-R; Package: SOT-5; Part_type: ICS\ANALOG\ACTIVE FILTER; Project: CENTAURUS; RoHS: RoHS; Temperature: -40°C+85°C; Tolerance: NA; Voltage: NA; Wattage: NA; Weight: 2.8mg; Datasheet: Y:\MIS_DATABASE\DATASHEETS\ICS\MISC\TPD2E001DRLR.PDF
U22 = SN74LVC1G11DCKR_SC70-6: IC SINGLE 3-INPUT POSITIVE-AND GATE SON6; Chkd/date: MANIRAJA/270121; Crtd /date: ALVY/270121; Custom_Duty: 15%; Customs_HS_Code: 85423100; Distributor_name: DIGIKEY; Distributor_part_number: 296-30120-1-ND; Footprint Path: Y:\MIS_DATABASE\Library\ALTIUM_TOOL\PCB_FOOTPRINTS\Altium_Footprint_Lib.PcbLib; Height: 0.60MM; Library Path: Y:\MIS_DATABASE\Library\ALTIUM_TOOL\SCHEMATICS_PARTS\MS_GATE_Library.schlib; Mfr_name: TEXAS INSTRUMENTS; Mistral Part No: 141021010013-R; Package: SON6; Part_type: ICS\DIGITAL\GATES; Project: AM64X_SKEVM; RoHS: RoHS; Temperature: -40°C+125°C; Tolerance: NA; Voltage: NA; Wattage: NA; Weight: 33mg; Datasheet: Y:\MIS_DATABASE\DATASHEETS\ICS\DIGITAL\GATES\SN74LVC1G_NOV16.PDF
U12 = AM62-EVM_BGA425: IC AM62 SoC MICROPROCESSOR BGA425; Chkd/date: ALVY/110621; Crtd /date: MANIRAJA/110621; Custom_Duty: 15%; Customs_HS_Code: 85423100; Distributor_name: NA; Distributor_part_number: NA; Footprint Path: Y:\MIS_DATABASE\Library\ALTIUM_TOOL\PCB_FOOTPRINTS\Altium_Footprint_Lib.PcbLib; Height: 0.65MM; Library Path: Y:\MIS_DATABASE\Library\ALTIUM_TOOL\SCHEMATICS_PARTS\MS_MICROPROCESSOR_Library.schlib; Mfr_name: TEXAS INSTRUMENTS; Mistral Part No: 141221060001; Package: BGA425; Part_type: ICS\DIGITAL\MICROPROCESSOR; Project: AM62_EVM_BRD; RoHS: NA; Temperature: NA; Tolerance: NA; Voltage: NA; Wattage: NA; Weight: NA; Datasheet: Y:\MIS_DATABASE\DATASHEETS\ICS\DIGITAL\MICROCONTROLLER\AM62-SoC_SVB.PDF

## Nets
DGND: C3.2 C4.1 C5.2 C6.1 C7.1 C9.2 C10.1 C46.2 C47.2 C60.1 C65.1 C66.1 C72.1 C94.2 C330.2 C331.2 C333.2 C335.2 C338.2 C341.2 C380.2 C528.2 C529.2 C531.1 C544.1 C545.1 J2.1(GND) J2.7(GND) J2.18(GND) J2.33(GND) J2.39(GND) J2.45(GND) J2.51(GND) J2.57(GND) J2.63(GND) J2.69(GND) J2.75(GND) J2.SH1 J2.SH2 J20.6(VSS) J20.SH1 J20.SH2 J20.SH3 J20.SH4 R12.2 R272.2 R333.2 R393.2 R398.2 R671.2 R700.1 U1.2(GND) U2.7(GND) U2.15(TAB) U13.5(GND) U15.5(GND) U18.4(GND) U22.2(GND) U28.A6(VSS) U28.C4(VSSQ) U28.E7(VSS) U28.G5(VSS) U28.H10(VSS) U28.J5(VSS) U28.K8(VSS) U28.N2(VSSQ) U28.N5(VSSQ) U28.P4(VSSQ) U28.P6(VSSQ) U58.3(GND) ; also on sheet 1 3 12 13 14 15 16 17 18 19 23 24 25 26 27 28 29 30 31 32 33 34 35 36 37 38 39 40 41 42 43 44 45
VCC_1V8: C7.2 C333.1 C341.1 C380.1 C529.1 R4.1 R6.1 R10.2 R18.2 R19.2 R20.2 R21.2 R22.2 R364.2 R365.2 R366.2 R367.2 R376.2 R377.2 R378.2 R379.2 R396.2 R399.1 R426.1 R703.2 U2.1(VCCA) U28.C6(VCCQ) U28.M4(VCCQ) U28.N4(VCCQ) U28.P3(VCCQ) U28.P5(VCCQ) U58.5(VCC) ; also on sheet 14 15 23 27 36 39 41 42 44
VCC_3V3_SYS: C3.1 C4.2 C6.2 C9.1 C10.2 C46.1 C94.1 C335.1 C338.1 C528.1 C531.2 C544.2 J2.2(3-3V) J2.4(3-3V) J2.72(3-3V) J2.74(3-3V) R3.1 R96.1 R117.2 R273.1 R374.2 R427.2 R701.2 R704.1 R715.2 U2.14(VCCB) U13.2(VIN1) U13.8(VBIAS) U18.1(VCC) U22.5(VCC) U28.E6(VCC) U28.F5(VCC) U28.J10(VCC) U28.K9(VCC) ; also on sheet 3 12 14 15 16 24 25 26 27 28 29 31 32 33 34 35 36 37 38 39 40 41 42 43 44 45
VDD_MMC1: C60.2 FL8.1 U13.7(VOUT1)
VDD_MMC1_SD: C65.2 C66.2 FL8.2 J20.4(VDD)
VDDIM: C330.1 C331.1 U28.C2(VDDIM)
VDDSHV_SDIO: C72.2 C545.2 R80.2 R81.2 R82.2 R90.2 R91.2 R92.2 U13.6(VOUT2) U15.10(VCC) ; also on sheet 1
BT_EN_SOC_3V3: J2.54(W_DISABLE2#) R273.2 ; also on sheet 36
BT_UART_WAKE_1V8: R2.2 U2.4(A3)
BT_UART_WAKE_CONN: J2.20(UART_WAKE#) R1.1 R2.1
BT_UART_WAKE_SOC_3V3: R1.2 R704.2 U2.11(B3) ; also on sheet 41
BT_WLAN_EN: J2.56(W_DISABLE1#) R23.2 R272.1 R702.2
eMMC_RSTn: R426.2 U28.K5(RST_N) U58.4(Y)
GPIO_eMMC_RSTn: R726.2 ; also on sheet 41
HFOSC0_CLKOUT_32K: R7.1 ; also on sheet 34
M2_LED1#: J2.6(LED_1#) TP3.1(TP)
M2_LED2#: J2.16(LED_2#) TP4.1(TP)
MCASP1_ACLKX_BT_1V8: J2.8(PCM_CLK/I2S_SCK) ; also on sheet 41
MCASP1_AFSX_BT_1V8: J2.10(PCM_SYNC/I2S_WS) ; also on sheet 41
MCASP1_AXR0_BT_1V8: J2.12(PCM_IN/I2S_SD_IN) R671.1 ; also on sheet 41
MCASP1_AXR2_BT_1V8: J2.14(PCM_OUT/I2S_SD_OUT) ; also on sheet 41
MMC0_CLK: R89.1 R398.1 R399.2 U28.M6(CLK)
MMC1_CLK: J20.5(CLK) R66.1 R90.1 R333.1 U15.6(IO4)
MMC1_CLK_R: R66.2 U12.B22(MMC1_CLK)
MMC1_CMD: J20.3(CMD) R82.1 U12.A21(MMC1_CMD) U15.1(IO1)
MMC1_D0: J20.7(DAT0) R92.1 U12.A22(MMC1_DAT0) U15.8(IO6)
MMC1_D1: J20.8(DAT1) R91.1 U12.B21(MMC1_DAT1) U15.7(IO5)
MMC1_D2: J20.1(DAT2) R81.1 U12.C21(MMC1_DAT2) U15.2(IO2)
MMC1_D3: J20.2(CD/DAT3) R80.1 U12.D22(MMC1_DAT3) U15.3(IO3)
MMC1_SD_EN: R727.2 ; also on sheet 41
MMC1_SD_LS_EN: R374.1 R776.1 R777.1 U22.4(Y)
MMC1_SDCD: J20.9(CD) R96.2 U12.D17(MMC1_SDCD) U18.5(IO2)
MMC2_CLK: J2.9(SDIO_CLK/SYSCLK) R10.1 R12.1 R57.2
MMC2_CMD: R282.2 U12.C24(MMC2_CMD)
MMC2_CMD_COM: J2.11(SDIO_CMD) R20.1 R282.1
MMC2_D0: R284.2 U12.B24(MMC2_DAT0)
MMC2_D0_COM: J2.13(SDIO_DATA0) R18.1 R284.1
MMC2_D1: R283.2 U12.C25(MMC2_DAT1)
MMC2_D1_COM: J2.15(SDIO_DATA1) R19.1 R283.1
MMC2_D2: R281.2 U12.E23(MMC2_DAT2)
MMC2_D2_COM: J2.17(SDIO_DATA2) R21.1 R281.1
MMC2_D3: R280.2 U12.D24(MMC2_DAT3)
MMC2_D3_COM: J2.19(SDIO_DATA3) R22.1 R280.1
PMIC_VDDSHV_SDIO: C47.1 U13.3(VIN2) ; also on sheet 15
PORz_OUT: U22.6(C) ; also on sheet 25 26 29 44
RESETSTATz: U22.3(B) U58.2(B) ; also on sheet 15 23 25 26 29 34 35 39 41 42 43 44
SLOW_CLK: J2.50(SUSCLK_32kHz) R5.2 R7.2
SOC_GPIO1_49: U12.C17(MMC1_SDWP) ; also on sheet 40
SOC_MMC0_CLK: R89.2 U12.AB1(MMC0_CLK)
SOC_MMC0_CMD: R396.1 U12.Y3(MMC0_CMD) U28.M5(CMD)
SOC_MMC0_DAT0: R378.1 U12.AA2(MMC0_DAT0) U28.A3(DAT0)
SOC_MMC0_DAT1: R377.1 U12.AA1(MMC0_DAT1) U28.A4(DAT1)
SOC_MMC0_DAT2: R376.1 U12.AA3(MMC0_DAT2) U28.A5(DAT2)
SOC_MMC0_DAT3: R379.1 U12.Y4(MMC0_DAT3) U28.B2(DAT3)
SOC_MMC0_DAT4: R367.1 U12.AB2(MMC0_DAT4) U28.B3(DAT4)
SOC_MMC0_DAT5: R366.1 U12.AC1(MMC0_DAT5) U28.B4(DAT5)
SOC_MMC0_DAT6: R365.1 U12.AD2(MMC0_DAT6) U28.B5(DAT6)
SOC_MMC0_DAT7: R364.1 U12.AC2(MMC0_DAT7) U28.B6(DAT7)
SoC_MMC2_CLK: R57.1 U12.D25(MMC2_CLK)
SOC_UART1_CTS_BT_1V8: J2.34(UART_CTS) ; also on sheet 39
SOC_UART1_RTS_BT_1V8: J2.36(UART_RTS) ; also on sheet 39
SOC_UART1_RX_BT_1V8: J2.22(UART_RXD) ; also on sheet 39
SOC_UART1_TX_BT_1V8: R24.2 ; also on sheet 39
SoC_WLAN_EN_1V8: R23.1 U2.3(A2) U12.A23(MMC2_SDCD)
SoC_WLAN_EN_3V3: R702.1 U2.12(B2)
SoC_WLAN_IRQ_1V8: J2.21(SDIO_WAKE#) R6.2 U12.B23(MMC2_SDWP)
USB_DM: J2.5(USB_D-) TP2.1(TP)
USB_DP: J2.3(USB_D+) TP1.1(TP)
WL_LT_EN: R700.2 R701.1 U2.8(OE) ; also on sheet 41
WLAN_ALERT_1V8: R11.2 U2.5(A4)
WLAN_ALERT_3V3: R715.1 U2.10(B4) ; also on sheet 41
WLAN_SDIO_RST_1V8: J2.23(SDIO_RESET#/TX_BLANKING) R703.1 U2.2(A1)
WLAN_SDIO_RST_3V3: U2.13(B1) ; also on sheet 41
N15951745: C5.1 R3.2 R4.2 U1.1(TRI-STATE) U1.4(VDD)
N15952254: R5.1 U1.3(OUTPUT)
N16848941: R427.1 R726.1 U58.1(A)
N16878497: R393.1 TP90.1(TP) U28.H5(DS)
N16880083: R117.1 R727.1 U22.1(A)
N20600664: J2.32(UART_TXD) R24.1
N20605838: J2.62(ALERT#) R11.1
N22382190: R776.2 U13.4(ON2)
N22382326: R777.2 U13.1(ON1)

Not connected (* = marked no-connect by the designer): J2 35(PETP0)* 37(PETN0)* 38(VENDOR_DEFINED1)* 40(VENDOR_DEFINED2)* 41(PERP0)* 42(VENDOR_DEFINED3)* 43(PERN0)* 44(COEX3)* 46(COEX_RXD)* 47(REFCLKP0)* 48(COEX_TXD)* 49(REFCLKN0)* 52(PERST0#)* 53(CLKREQ0#)* 55(PEWAKE0#)* 58(I2C_DATA)* 59(RESERVED/PETP1)* 60(I2C_CLK)* 61(RESERVED/PETN1)* 64(RESERVED)* 65(RESERVED/PERP1)* 66(UIM_SWP/PERST1#)* 67(RESERVED/PERN1)* 68(UIM_POWER_SNK/CLKREQ1#)* 70(UIM_POWER_SRC/GPIO1/PEWAKE#)* 71(RESERVED/REFCLKP1)* 73(RESERVED/REFCLKN1)* SH3*; U2 6(NC1)* 9(NC2)*; U15 4(NC1)* 9(NC2)*; U18 2(NC)* 3(IO1)*; U28 A1(NC1)* A2(NC2)* A7(RFU1)* A8(NC3)* A9(NC4)* A10(NC5)* A11(NC6)* A12(NC7)* A13(NC8)* A14(NC9)* B1(NC10)* B7(NC11)* B8(NC12)* B9(NC13)* B10(NC14)* B11(NC15)* B12(NC16)* B13(NC17)* B14(NC18)* C1(NC19)* C3(NC20)* C5(NC21)* C7(NC22)* C8(NC23)* C9(NC24)* C10(NC25)* C11(NC26)* C12(NC27)* C13(NC28)* C14(NC29)* D1(NC30)* D2(NC31)* D3(NC32)* D4(NC33)* D12(NC34)* D13(NC35)* D14(NC36)* E1(NC37)* E2(NC38)* E3(NC39)* E5(RFU2)* E8(VSF1)* E9(VSF2)* E10(VSF3)* E12(NC40)* E13(NC41)* E14(NC42)* F1(NC43)* F2(NC44)* F3(NC45)* F10(VSF4)* F12(NC46)* F13(NC47)* F14(NC48)* G1(NC49)* G2(NC50)* G3(NC51)* G10(VSF5)* G12(NC52)* G13(NC53)* G14(NC54)* H1(NC55)* H2(NC56)* H3(NC57)* H12(NC58)* H13(NC59)* H14(NC60)* J1(NC61)* J2(NC62)* J3(NC63)* J12(NC64)* J13(NC65)* J14(NC66)* K1(NC67)* K2(NC68)* K3(NC69)* K6(RFU3)* K7(RFU4)* K10(VSF6)* K12(NC70)* K13(NC71)* K14(NC72)* L1(NC73)* L2(NC74)* L3(NC75)* L12(NC76)* L13(NC77)* L14(NC78)* M1(NC79)* M2(NC80)* M3(NC81)* M7(NC82)* M8(NC83)* M9(NC84)* M10(NC85)* M11(NC86)* M12(NC87)* M13(NC88)* M14(NC89)* N1(NC90)* N3(NC91)* N6(NC92)* N7(NC93)* N8(NC94)* N9(NC95)* N10(NC96)* N11(NC97)* N12(NC98)* N13(NC99)* N14(NC100)* P1(NC101)* P2(NC102)* P7(NC103)* P8(NC104)* P9(NC105)* P10(VSF7)* P11(NC106)* P12(NC107)* P13(NC108)* P14(NC109)*

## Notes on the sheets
sheet 20
- M.2 INTERFACE
- 1.8V
- 1.8V
- V
- CAD Note:
  Place the termination resistors closer to the SoC.
- D-Note:
  Series resistors for the SDIO
  interface signals are optional
  on the custom board
- V
- SoC_MAIN_UART1_RXD
- SoC_MAIN_UART1_TXD
- SoC_MAIN_UART1_CTS
- 1.8V
- SoC_MAIN_UART1_RTS
- D-Note:
  Add a bulk cap near to the oscillator
  supply pin when oscillator is populated
  and used
- CAD Note:
  Place R5 & R7 close to
  each other to avoid stub.
- V
- D-Note:
  Verify availability of pulls internal to the attached device
- D-Note:
  Use standard tolerance 8.2K resistor
- WL_LT_EN = Active High
- D-Note:
  R700 and R701 acts as a voltage divider to
  source 1.8V I/O pin (since OE refers to VCCA)
  from 3.3V output of I/O Expander.
sheet 21
- SOC - MMC Interface
- D-Note:
  0E provision on MMC0_CLK has been
  provided for control of possible signal reflections
- D-Note:
  Refer Custom Board Design and Simulation Guidelines for
  Processor High Speed Parallel Interfaces
  https://www.ti.com/lit/pdf/sdaa087
- eMMC FLASH
- D-Note:
  MMC0 interface is compliant with
  the JEDEC eMMC electrical
  standard v5.1 (JESD84-B51).
- D-Note:
  The pull-up required for D7-D0, clock and
  other eMMC interface control signals are
  enabled internal to the SoC during reset
  and are eMMC JEDEC standard compliant.
  External pull-up is optional and can be
  deleted on the custom board. Refer to the
  pin connectivity requirements section for
  connecting the eMMC interface when not
  used.
- D-Note:
  The processor family implements a soft PHY for
  eMMC interface. The pulls required for D0,
  clock and other eMMC interface control signals
  are recommended to be implemented externally.
- D-Note:
  0E provision on MMC1_CLK has been
  provided for control of possible signal reflections
- C
- C
- D-Note:
  As a good design practice, a 47K pull-up
  is recommended to ensure the pull-up
  value is within the JEDEC specification,
  when internal pulls are enabled unexpectedly.
  This way the resulting pull resistance will still
  be within the specified limits.
- GPIO1_49
- V
- D-Note:
  0E provision on MMC2_CLK has been
  provided for control of possible signal reflections
- 1.8V
- R-Note:
  What is the reason  pulldown is used  for eMMC,
  SD card or other peripherals clock input?
  Because, there are cases where the clock is
  stopped or paused in a LOW logic state, and the
  pull-down option is consistent with this logic
  state.
- eMMC FLASH RESET
- D-Note:
  Ensure that eMMC_RSTn reset input is
  enabled in the eMMC device (eMMC
  non-volatile configuration space) for
  the reset logic to be functional.
- D-Note:
  The GPIO reset option makes it possible for the
  software to reset the attached device (eMMC or
  OSPI or SD card or OLDI or EPHY) without
  resetting the entire processor, if there is a
  case where the peripheral becomes unresponsive.
- V
- D-Note:
  You could eliminate the GPIO option and only
  use the reset output (warm or cold), where the
  software forces a warm reset, if the peripheral
  becomes unresponsive. However, this will reset
  the entire device, rather than trying to
  recover the specific peripheral without
  resetting the entire device.
- D-Note:
  In case ANDing logic is not used and the processor Main
  domain warm reset status output (RESETSTATz) is used
  to reset the attached device, ensure the IO voltage level of
  the attached device matches the RESETSTATz IO voltage
  level. A level translator is recommended to match the IO
  voltage level. A resistor divider can be used  alternatively,
  provided optimum impedance value of the resistor divider is
  selected. In case the value is too high, the rise/fall time of
  the eMMC reset input can be slow and introduce too much
  delay. In case the value is too low, it will cause the AM62x to
  source too much steady-state current during normal
  operation.
- D-Note:
  ANDing logic additionally performs level translation.
  Verify the reset IO level compatibility before optimizing
  the reset ANDing logic. IO level mismatch can cause
  residual voltage (supply leakage) and affect PMIC/SoC
  operation.
sheet 22
- SD CARD INTERFACE
- D-Note:
  SD card power control power switch, along with the SD care power swutrch EN reset logic and the host
  switched IO power supply circuit, is required to support UHS-I SD Card which begins communication
  using 3.3 V IO signal level which later switches to 1.8 V signal level when changing to a faster
  data transfer speed. Cycling power to the SD Card is the only way to put the SD card back into
  3.3 V mode since SD Cards do not have a reset pin. The host IO power supply must power off/on and
  change voltage at the same time as the SD Card. These circuits and the software driver operating
  the signals sourcing these circuits ensure both devices are off or on and are operating at the
  same IO voltage at the same time.
- D-Note:
  Refer Custom Board Design and Simulation Guidelines for
  Processor High Speed Parallel Interfaces
  https://www.ti.com/lit/pdf/sdaa087
- SD CARD LOAD SWITCH EN RESET LOGIC
- LOAD SWITCH
- D-Note:
  Series resistor is used
  for control of rise time
- D-Note:
  Dual-channel load switch is used
  to provide provision to reset the
  SD card supply, and  dynamically
  switched Dual-voltage IO supply
   connected  to the processor
  SD card IO supply for IO group
  VDDSHV5 and the SD card IO pullups.
- D-Note:
  ANDing logic could be optimized to a 2-input AND gate.
  Use RESETSTATz and the SoC IO as inputs to the
  ANDing logic.
- C
- D-Note:
  For UHS-I SD card support, the
  pull-ups are recommended to be
  connected to the 3.3V/1.8 V
  switched LDO output.
- Note:
  MMC1_CLK pull-up is a DNI.
- D-Note:
  As a good design practice, a 47K pull-up is
  recommended to ensure the pull-up value is within
  the SD card specification, when internal pulls are
  enabled unexpectedly. This way the resulting pull
  resistance will still be within the specified limits.
- V
- D-Note:
  Add a 100R series resistor for the
  MMC1_SDCD signal. Processor
  IO SDCD directly connects to
  ground when SD card is inserted
- CAD Note:
  Place R333 near to the SD card connector
- C
- CAD Note:
  Place near the SD card connector.
